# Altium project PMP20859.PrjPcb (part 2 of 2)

## Sheet PMP20859_RevF_SH3.SchDoc: Synchronous Flyback Converter
size 431 x 279 mm; Date: Not shown in title block; ApprovedBy: Not shown in title block; CheckedBy: Not shown in title block; Author: Not shown in title block; CompanyName: Not shown in title block; Engineer: Not shown in title block; Organization: Not shown in title block; Address1: Not shown in title block; Address2: Not shown in title block; Address3: Not shown in title block; Address4: Not shown in title block; DocumentNumber: 3; Revision: Use project parameter SCH_Rev; SheetNumber: 3; SheetTotal: 3; PageSetup: Record=PageOptions¦CenterHorizontal=True¦CenterVertical=True¦PrintScale=1.00¦XCorrection=1.00¦YCorrection=1.00¦PrintKind=0¦BorderSize=5000000¦LeftOffset=0¦BottomOffset=0¦Orientation=2¦PaperLength=1000¦PaperWidth=1000¦Scale=100¦PaperSource=15¦PrintQuality=600¦MediaType=1¦DitherType=10¦PaperKind=Letter¦PrintScaleMode=1
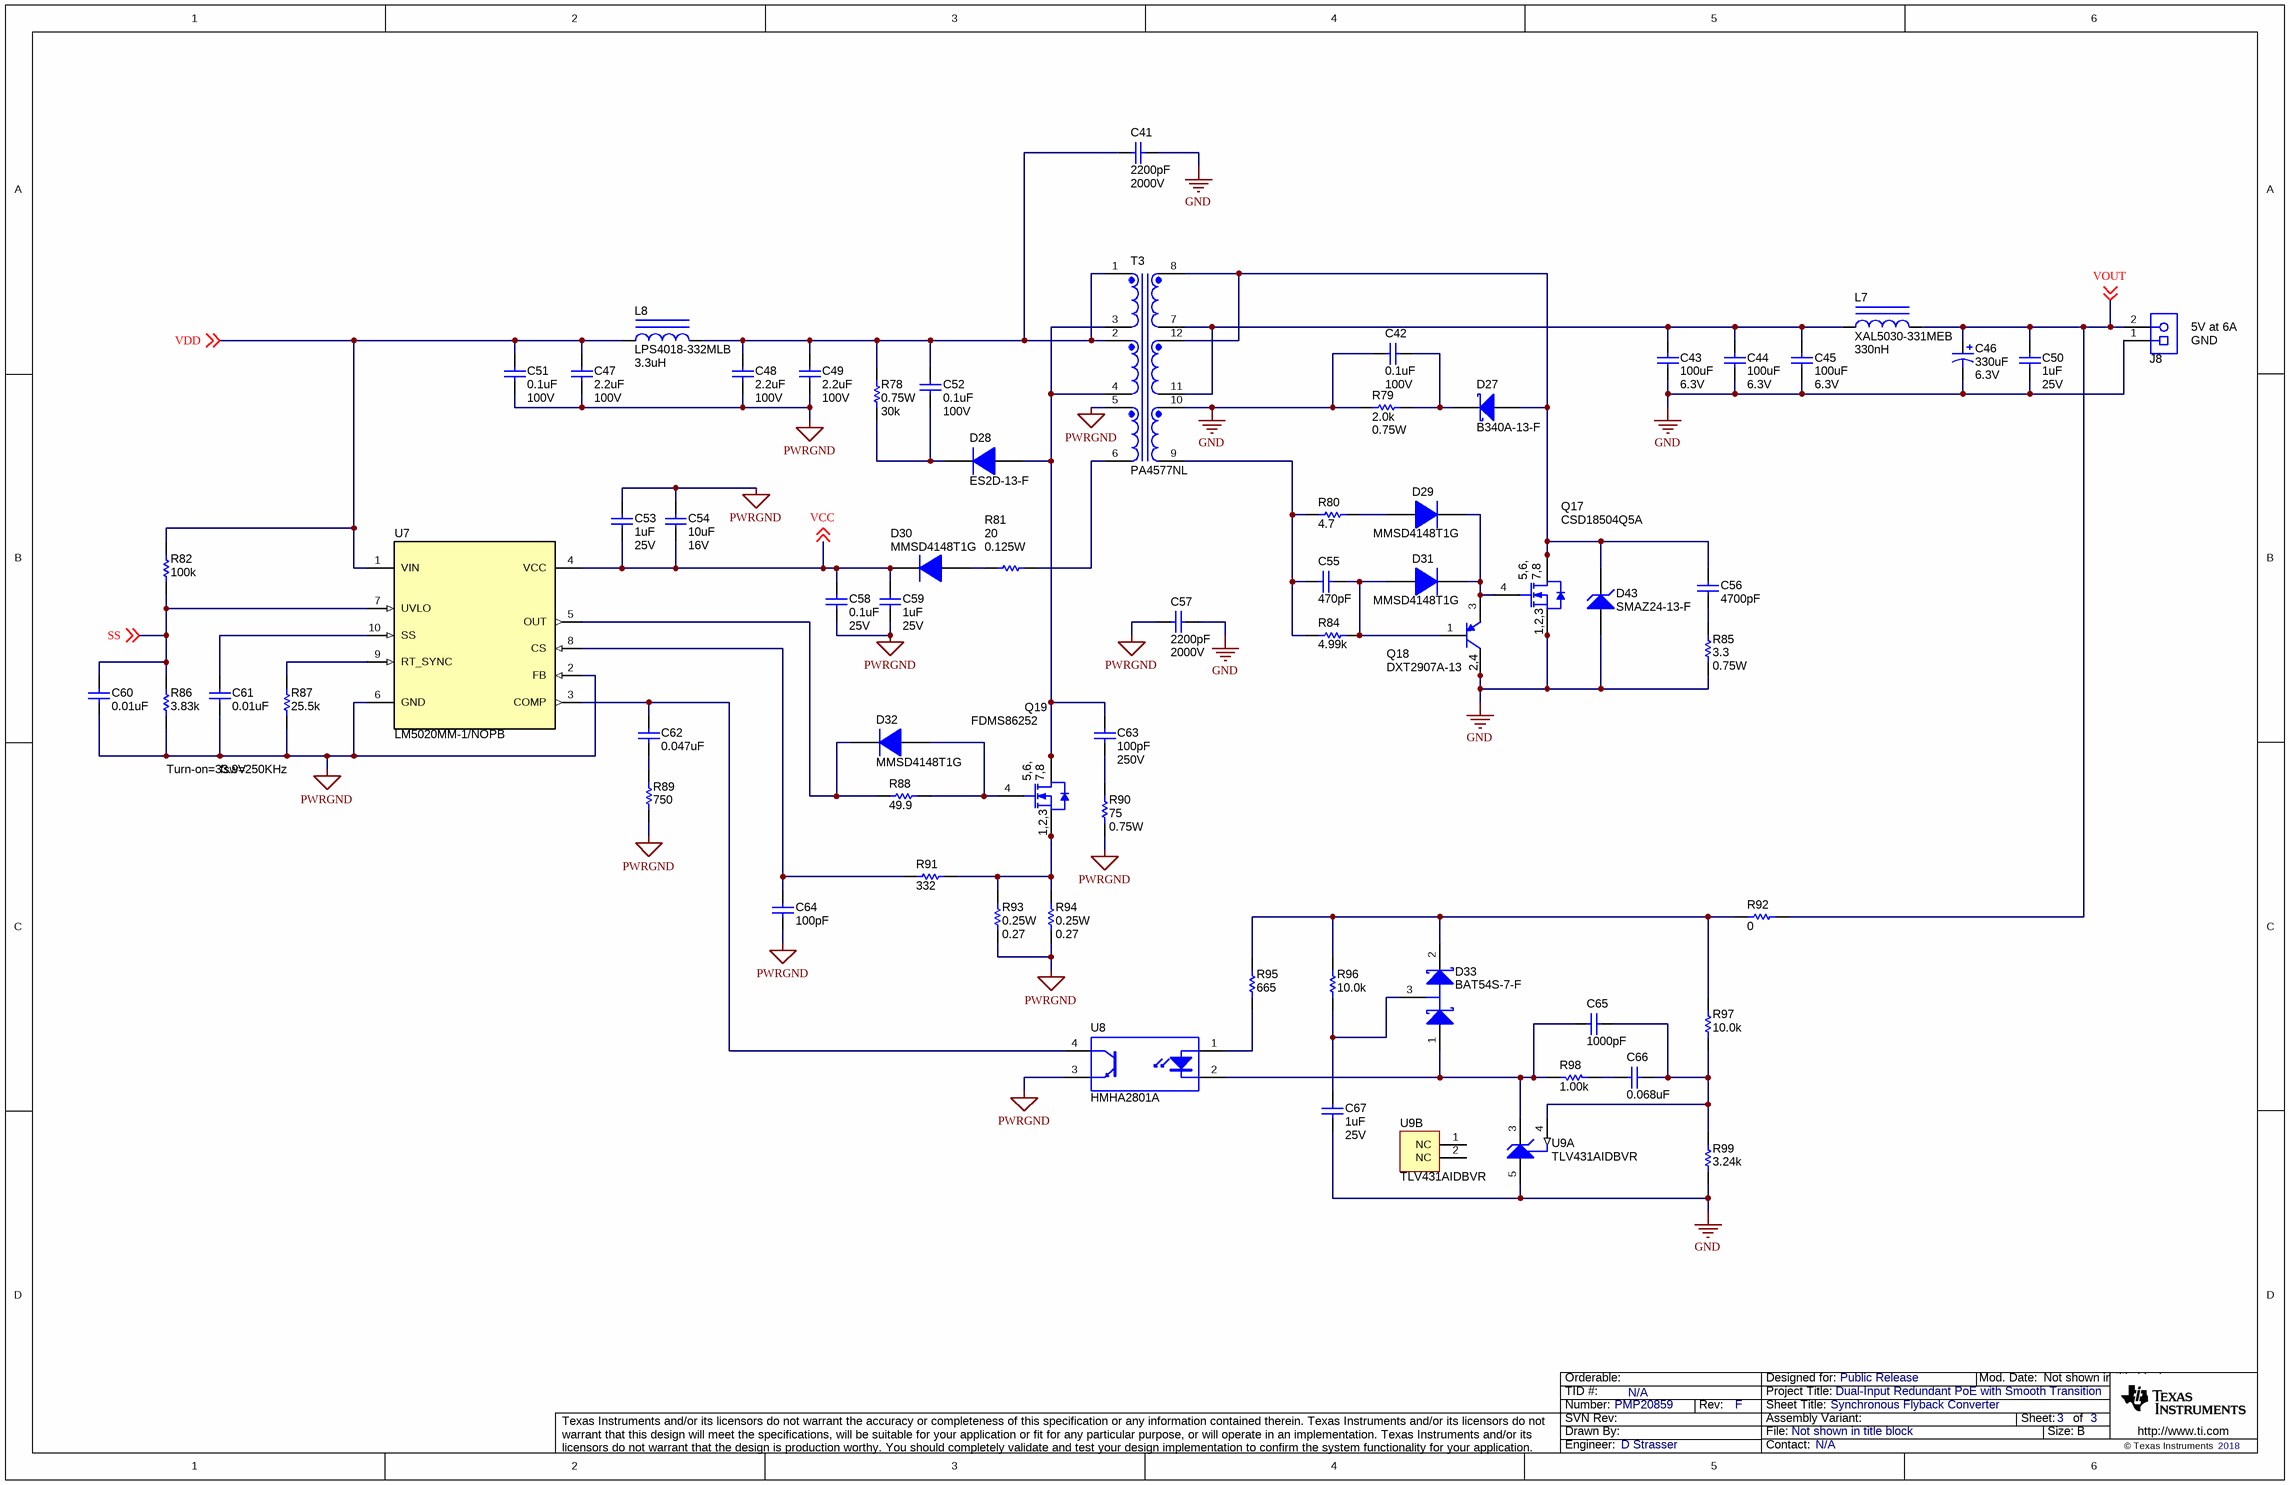
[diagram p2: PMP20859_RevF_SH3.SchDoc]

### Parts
C41  ValueDisplayed: 2200pF  Value2: 2000V  [1812]  (hidden comment: Capacitor)
C42  ValueDisplayed: 0.1uF  Value2: 100V  [0805_HV]  (hidden comment: Capacitor)
C43  ValueDisplayed: 100uF  Value2: 6.3V  [1210_280]  (hidden comment: Capacitor)
C44  ValueDisplayed: 100uF  Value2: 6.3V  [1210_280]  (hidden comment: Capacitor)
C45  ValueDisplayed: 100uF  Value2: 6.3V  [1210_280]  (hidden comment: Capacitor)
C46  ValueDisplayed: 330uF  Value2: 6.3V  [SM_RADIAL_10AMM]  (hidden comment: Cap_Polarized)
C47  ValueDisplayed: 2.2uF  Value2: 100V  [1210_270]  (hidden comment: Capacitor)
C48  ValueDisplayed: 2.2uF  Value2: 100V  [1210_270]  (hidden comment: Capacitor)
C49  ValueDisplayed: 2.2uF  Value2: 100V  [1210_270]  (hidden comment: Capacitor)
C50  ValueDisplayed: 1uF  Value2: 25V  [0805_HV]  (hidden comment: Capacitor)
C51  ValueDisplayed: 0.1uF  Value2: 100V  [0805_HV]  (hidden comment: Capacitor)
C52  ValueDisplayed: 0.1uF  Value2: 100V  [0805_HV]  (hidden comment: Capacitor)
C53  ValueDisplayed: 1uF  Value2: 25V  [0805_HV]  (hidden comment: Capacitor)
C54  ValueDisplayed: 10uF  Value2: 16V  [1206_190]  (hidden comment: Capacitor)
C55  ValueDisplayed: 470pF  [0603L]  (hidden comment: Capacitor)
C56  ValueDisplayed: 4700pF  [0603L]  (hidden comment: Capacitor)
C57  ValueDisplayed: 2200pF  Value2: 2000V  [1812]  (hidden comment: Capacitor)
C58  ValueDisplayed: 0.1uF  VDC_V: 25V  [0603]  (hidden comment: C1608X7R1E104K080AA)
C59  ValueDisplayed: 1uF  Value2: 25V  [0805_HV]  (hidden comment: Capacitor)
C60  ValueDisplayed: 0.01uF  [0603L]  (hidden comment: Capacitor)
C61  ValueDisplayed: 0.01uF  [0603L]  (hidden comment: Capacitor)
C62  ValueDisplayed: 0.047uF  [0603L]  (hidden comment: Capacitor)
C63  ValueDisplayed: 100pF  Value2: 250V  [0805_HV]  (hidden comment: Capacitor)
C64  ValueDisplayed: 100pF  [0603L]  (hidden comment: Capacitor)
C65  ValueDisplayed: 1000pF  [0603L]  (hidden comment: Capacitor)
C66  ValueDisplayed: 0.068uF  [0603L]  (hidden comment: Capacitor)
C67  ValueDisplayed: 1uF  Value2: 25V  [0805_HV]  (hidden comment: Capacitor)
D27  B340A-13-F  [SMA]
D28  ES2D-13-F  [SMB]
D29  MMSD4148T1G  [SOD-123]
D30  MMSD4148T1G  [SOD-123]
D31  MMSD4148T1G  [SOD-123]
D32  MMSD4148T1G  [SOD-123]
D33  BAT54S-7-F  [SOT-23]
D43  SMAZ24-13-F  [SMA]
J8  ED555/2DS  [TERM_BLK_ED555-2DS]  (value not drawn)
L7  XAL5030-331MEB  ValueDisplayed: 330nH  [XAL5030]
L8  LPS4018-332MLB  value 3.3uH  [LPS4018]
Q17  CSD18504Q5A  [DQJ0008A]
Q18  DXT2907A-13  [SOT-89-3]
Q19  FDMS86252  [TRANS_Fairchild_PQFN08A]
R78  Value2: 0.75W  ValueDisplayed: 30k  [2010L]  (hidden comment: Resistor)
R79  ValueDisplayed: 2.0k  Value2: 0.75W  [2010L]  (hidden comment: Resistor)
R80  ValueDisplayed: 4.7  [0603L]  (hidden comment: Resistor)
R81  value 20  Value2: 0.125W  [0805_HV]  (hidden comment: Resistor)
R82  ValueDisplayed: 100k  [0603L]  (hidden comment: Resistor)
R84  value 4.99k  [0603L]  (hidden comment: Resistor)
R85  ValueDisplayed: 3.3  Value2: 0.75W  [2010L]  (hidden comment: Resistor)
R86  ValueDisplayed: 3.83k  [0603L]  (hidden comment: Resistor)
R87  ValueDisplayed: 25.5k  [0603L]  (hidden comment: Resistor)
R88  ValueDisplayed: 49.9  [0603L]  (hidden comment: Resistor)
R89  ValueDisplayed: 750  [0603L]  (hidden comment: Resistor)
R90  ValueDisplayed: 75  Value2: 0.75W  [2010L]  (hidden comment: Resistor)
R91  value 332  [0603L]  (hidden comment: Resistor)
R92  ValueDisplayed: 0  [0603]  (hidden comment: Resistor)
R93  Value2: 0.25W  ValueDisplayed: 0.27  [1206L]  (hidden comment: Resistor)
R94  Value2: 0.25W  ValueDisplayed: 0.27  [1206L]  (hidden comment: Resistor)
R95  ValueDisplayed: 665  [0603L]  (hidden comment: Resistor)
R96  ValueDisplayed: 10.0k  [0603L]  (hidden comment: Resistor)
R97  ValueDisplayed: 10.0k  [0603L]  (hidden comment: Resistor)
R98  ValueDisplayed: 1.00k  [0603L]  (hidden comment: Resistor)
R99  ValueDisplayed: 3.24k  [0603L]  (hidden comment: Resistor)
T3  PA4577NL  [Pulse_PA4577NL]
U7  LM5020MM-1/NOPB  [DGS0010A_N]
U8  HMHA2801A  [MFP04A]
U9  TLV431AIDBVR  [DBV0005A_N]  (parts A,B of 2)

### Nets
GND: C41.2 C42.1 C43.2 C44.2 C45.2 C46.2(-) C50.2 C57.2 C67.2 D43.2(A) J8.1 Q17.1(S) Q17.2(S) Q17.3(S) Q18.2(C) Q18.4(C) R79.2 R85.1 R99.1 T3.10 U9.5(ANODE)
PWRGND: C47.2 C48.2 C49.2 C51.2 C53.1 C54.2 C57.1 C58.2 C59.2 C60.1 C61.1 C64.2 R86.1 R87.1 R89.1 R90.1 R93.1 R94.1 T3.5 U7.2(FB) U7.6(GND) U8.3(E)
SS: C60.2 R82.1 R86.2 U7.7(UVLO) ; off-sheet SS
VCC: C53.2 C54.1 C58.1 C59.1 D30.1(K) U7.4(VCC) ; off-sheet VCC
VDD: C47.1 C51.1 L8.1 R82.2 U7.1(VIN) ; off-sheet VDD
VOUT: C46.1(+) C50.1 J8.2 L7.2 R92.1 ; off-sheet VOUT
NetC41_1: C41.1 C48.1 C49.1 C52.1 L8.2 R78.2 T3.1 T3.2
NetC42_2: C42.2 D27.1(K) R79.1
NetC43_1: C43.1 C44.1 C45.1 L7.1 T3.7 T3.11
NetC52_2: C52.2 D28.1(K) R78.1
NetC55_1: C55.1 R80.2 R84.2 T3.9
NetC55_2: C55.2 D31.2(A) Q18.1(B) R84.1
NetC56_1: C56.1 R85.2
NetC56_2: C56.2 D27.2(A) D43.1(K) Q17.5(D) Q17.6(D) Q17.7(D) Q17.8(D) Q17.9(D) T3.8 T3.12
NetC61_2: C61.2 U7.10(SS)
NetC62_1: C62.1 R89.2
NetC62_2: C62.2 U7.3(COMP) U8.4(C)
NetC63_1: C63.1 D28.2(A) Q19.5(D) Q19.6(D) Q19.7(D) Q19.8(D) T3.3 T3.4
NetC63_2: C63.2 R90.2
NetC64_1: C64.1 R91.1 U7.8(CS)
NetC65_1: C65.1 C66.2 R97.2 R99.2 U9.4(REF)
NetC65_2: C65.2 D33.1(A) R98.2 U8.2(K) U9.3(CATHODE)
NetC66_1: C66.1 R98.1
NetC67_1: C67.1 D33.3(C) R96.1
NetD29_1: D29.1(K) D31.1(K) Q17.4(G) Q18.3(E)
NetD29_2: D29.2(A) R80.1
NetD30_2: D30.2(A) R81.1
NetD32_1: D32.1(K) R88.2 U7.5(OUT)
NetD32_2: D32.2(A) Q19.4(G) R88.1
NetD33_2: D33.2(K) R92.2 R95.2 R96.2 R97.1
NetQ19_1: Q19.1(S) Q19.2(S) Q19.3(S) R91.2 R93.2 R94.2
NetR81_2: R81.2 T3.6
NetR87_2: R87.2 U7.9(RT_SYNC)
NetR95_1: R95.1 U8.1(A)

Not connected (* = marked no-connect by the designer): U9 1(NC) 2(NC)

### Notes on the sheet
- (near J8) GND
- (near J8) 5V at 6A
- Turn-on=33.9V
- fsw=250KHz

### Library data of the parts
C41 C57 = CMP-0009358-2: CAP, CERM, 2200 pF, 2000 V, +/- 10%, X7R, 1812; PartNumber: C4532X7R3D222K130KA; Manufacturer: TDK; Polarized: N; Value: 2200pF; U/M: EA; Cap_F: 2.2nF; Value1: Unknown; VDC_V: 2kV; TaMin_C: -55°C; TaMax_C: 125°C; SizeArea_mm2: 14.4; SizeAreaWB_mm2: 23.1; SizeX_mm: 4.5; SizeY_mm: 3.2; SizeZ_mm: 1.35; AEC Category: Q200
C42 C51 C52 = CMP-0007886-2: CAP, CERM, 0.1 uF, 100 V, +/- 10%, X7R, 0805; PartNumber: C2012X7R2A104K125AA; Manufacturer: TDK; Polarized: N; Value: 0.1uF; U/M: EA; Cap_F: 100nF; ESR_ohm: 0.020726; Value1: 0.020726 ohm; IRMS_A: 1.456A; TaMin_C: -55°C; TaMax_C: 125°C; Cap_Case: 0805; AEC Category: Q200; SizeArea_mm2: 2.5; SizeAreaWB_mm2: 6.75; SizeX_mm: 2; SizeY_mm: 1.25; SizeZ_mm: 1.45
C43-C45 = CMP-0009098-2: CAP, CERM, 100 uF, 6.3 V, +/- 20%, X5R, 1210; PartNumber: C3225X5R0J107M250AC; Manufacturer: TDK; Polarized: N; Value: 100uF; U/M: EA; Cap_F: 100µF; ESR_ohm: 5.496m; Value1: 0.005496 ohm; IRMS_A: 3.13651A; TaMin_C: -55°C; TaMax_C: 85°C; SizeArea_mm2: 8; SizeAreaWB_mm2: 14.7; SizeX_mm: 3.2; SizeY_mm: 2.5; SizeZ_mm: 2.8; AEC Category: Q200
C46 = CMP-0012153-3: CAP, Aluminum Polymer, 330 uF, 6.3 V, +/- 20%, 0.025 ohm, 10x10.3 SMD; PartNumber: 6SVP330M; Manufacturer: Panasonic; Polarized: Y; CompType: Capacitor; Value: 330uF; Cap_F: 330µF; ESR_ohm: 0.025; IRMS_A: 3.7A; TaMin_C: -55°C; TaMax_C: 105°C; Cap_Case: 10.3x10.3x7.9; AEC Category: Q200; SizeArea_mm2: 113.3; SizeAreaWB_mm2: 159.9; SizeX_mm: 11; SizeY_mm: 10.3; SizeZ_mm: 7.7
C47-C49 = CMP-0009232-2: CAP, CERM, 2.2 uF, 100 V, +/- 10%, X7R, 1210; PartNumber: GRM32ER72A225KA35L; Manufacturer: MuRata; Polarized: N; Value: 2.2uF; U/M: EA; Cap_F: 2.2µF; ESR_ohm: 7m; Value1: 0.007 ohm; IRMS_A: 4.4A; TaMin_C: -55°C; TaMax_C: 125°C; Cap_Case: 1210; SizeArea_mm2: 8; SizeAreaWB_mm2: 14.7; SizeX_mm: 3.2; SizeY_mm: 2.5; SizeZ_mm: 2.7; AEC Category: Q200
C50 C53 C59 C67 = CMP-0008336-2: CAP, CERM, 1 uF, 25 V, +/- 10%, X7R, 0805; PartNumber: GRM21BR71E105KA99L; Manufacturer: MuRata; Polarized: N; Value: 1uF; U/M: EA; Cap_F: 1µF; Value1: Unknown; TaMin_C: -55°C; TaMax_C: 125°C; Cap_Case: 0805; SizeArea_mm2: 2.5; SizeAreaWB_mm2: 6.75; SizeX_mm: 2; SizeY_mm: 1.25; SizeZ_mm: 1.45; AEC Category: Q200
C54 = CMP-0008690-2: CAP, CERM, 10 uF, 16 V, +/- 10%, X7R, 1206_190; PartNumber: C3216X7R1C106K160AC; Manufacturer: TDK; Polarized: N; Value: 10uF; U/M: EA; Cap_F: 10µF; Value1: Unknown; TaMin_C: -55°C; TaMax_C: 125°C; Cap_Case: 1206; AEC Category: Q200; SizeArea_mm2: 5.12; SizeAreaWB_mm2: 10.92; SizeX_mm: 3.2; SizeY_mm: 1.6; SizeZ_mm: 1.9
C55 = CMP-0007221-4: CAP, CERM, 470 pF, 50 V, +/- 5%, C0G/NP0, 0603; PartNumber: GRM1885C1H471JA01D; Manufacturer: MuRata; Polarized: N; Value: 470pF; U/M: EA; Value1: Unknown; VDC_V: 50V; TaMin_C: -55°C; TaMax_C: 125°C; Cap_Case: 0603; SizeArea_mm2: 1.28; SizeAreaWB_mm2: 4.68; SizeX_mm: 1.6; SizeY_mm: 0.8; SizeZ_mm: 1; AEC Category: Q200
C56 = CMP-0007456-4: CAP, CERM, 4700 pF, 50 V, +/- 10%, X7R, 0603; PartNumber: GRM188R71H472KA01D; Manufacturer: MuRata; Polarized: N; Value: 4700pF; U/M: EA; Cap_F: 4.7nF; Value1: Unknown; VDC_V: 50V; TaMin_C: -55°C; TaMax_C: 125°C; Cap_Case: 0603; AEC Category: Q200; SizeArea_mm2: 1.28; SizeAreaWB_mm2: 4.68; SizeX_mm: 1.6; SizeY_mm: 0.8; SizeZ_mm: 1
C58 = CMP-0007039-5: CAP, CERM, 0.1 uF, 25 V, +/- 10%, X7R, 0603; Manufacturer: TDK; Polarized: N; CompType: Capacitor; Value: 0.1uF; U/M: EA; Cap_F: 100nF; Value1: Unknown; TaMin_C: -55°C; TaMax_C: 125°C; SizeArea_mm2: 1.28; SizeAreaWB_mm2: 4.68; SizeX_mm: 1.6; SizeY_mm: 0.8; SizeZ_mm: 1; AEC Category: Q200
C60 C61 = CMP-0007043-4: CAP, CERM, 0.01 uF, 50 V, +/- 10%, X7R, 0603; PartNumber: C1608X7R1H103K080AA; Manufacturer: TDK; Polarized: N; Value: 0.01uF; U/M: EA; Cap_F: 10nF; ESR_ohm: 0.0539; Value1: 0.0539 ohm; VDC_V: 50V; TaMin_C: -55°C; TaMax_C: 125°C; Cap_Case: 0603; SizeArea_mm2: 1.28; SizeAreaWB_mm2: 4.68; SizeX_mm: 1.6; SizeY_mm: 0.8; SizeZ_mm: 1; AEC Category: Q200
C62 = CMP-0007049-4: CAP, CERM, 0.047 uF, 50 V, +/- 10%, X7R, 0603; PartNumber: C1608X7R1H473K080AA; Manufacturer: TDK; Polarized: N; U/M: EA; Cap_F: 47nF; ESR_ohm: 0.049007; Value1: 0.049007 ohm; VDC_V: 50V; IRMS_A: 7.67528dA; TaMin_C: -55°C; TaMax_C: 125°C; Cap_Case: 0603; AEC Category: Q200; SizeArea_mm2: 1.28; SizeAreaWB_mm2: 4.68; SizeX_mm: 1.6; SizeY_mm: 0.8; SizeZ_mm: 1
C63 = CMP-0008236-2: CAP, CERM, 100 pF, 250 V, +/- 5%, C0G/NP0, 0805; PartNumber: GRM21A5C2E101JW01D; Manufacturer: MuRata; Polarized: N; Value: 100pF; U/M: EA; Value1: Unknown; TaMin_C: -55°C; TaMax_C: 125°C; Cap_Case: 0805; AEC Category: Q200; SizeArea_mm2: 2.5; SizeAreaWB_mm2: 6.75; SizeX_mm: 2; SizeY_mm: 1.25; SizeZ_mm: 1.45
C64 = CMP-0007171-4: CAP, CERM, 100 pF, 50 V, +/- 5%, C0G/NP0, 0603; PartNumber: GRM1885C1H101JA01D; Manufacturer: MuRata; Polarized: N; Value: 100pF; U/M: EA; Value1: Unknown; VDC_V: 50V; TaMin_C: -55°C; TaMax_C: 125°C; Cap_Case: 0603; AEC Category: Q200; SizeArea_mm2: 1.28; SizeAreaWB_mm2: 4.68; SizeX_mm: 1.6; SizeY_mm: 0.8; SizeZ_mm: 1
C65 = CMP-0007432-5: CAP, CERM, 1000 pF, 50 V, +/- 10%, X7R, 0603; PartNumber: GRM188R71H102KA01D; Manufacturer: MuRata; Polarized: N; Value: 1000pF; U/M: EA; Cap_F: 1nF; Value1: Unknown; VDC_V: 50V; TaMin_C: -55°C; TaMax_C: 125°C; Cap_Case: 0603; AEC Category: Q200; SizeArea_mm2: 1.28; SizeAreaWB_mm2: 4.68; SizeX_mm: 1.6; SizeY_mm: 0.8; SizeZ_mm: 1
C66 = CMP-0007428-4: CAP, CERM, 0.068 uF, 25 V, +/- 10%, X7R, 0603; PartNumber: GRM188R71E683KA01D; Manufacturer: MuRata; Polarized: N; U/M: EA; Cap_F: 68nF; Value1: Unknown; VDC_V: 25V; TaMin_C: -55°C; TaMax_C: 125°C; Cap_Case: 0603; AEC Category: Q200; SizeArea_mm2: 1.28; SizeAreaWB_mm2: 4.68; SizeX_mm: 1.6; SizeY_mm: 0.8; SizeZ_mm: 1
D27 = CMP-0028353-1: Diode, Schottky, 40 V, 3 A, SMA; Manufacturer: Diodes Inc.; U/M: EA; Vf_V: 5dV; Value: 40V; Value1: 3A; Value2: 0.5V; TJmax_C: 125°C; RJC_CperW: 25; AEC Category: Q101; Green_Lifecycle: Active; Green_REACh: Passed; SizeArea_mm2: 16.3228; SizeAreaWB_mm2: 37.3428; SizeX_mm: 5.59; SizeY_mm: 2.92; SizeZ_mm: 2.87
D28 = CMP-0076890-1: Diode, Ultrafast, 200 V, 2 A, SMB; Manufacturer: Diodes Inc.; Value: 200V; U/M: EA; Vf_V: 9.2dV; Value1: 2A; Value2: 0.92V; TJmax_C: 150°C; RJC_CperW: 20.0; AEC Category: Q101; Green_Lifecycle: Active; Green_REACh: Passed; SizeArea_mm2: 21.336; SizeAreaWB_mm2: 44.156; SizeX_mm: 5.6; SizeY_mm: 3.81; SizeZ_mm: 2.6
D29-D32 = CMP-0029032-1: Diode, Switching, 100 V, 0.2 A, SOD-123; Manufacturer: ON Semiconductor; Value: 100V; U/M: EA; Vf_V: 1V; Value1: 0.2A; Io_A: 2dA; TJmax_C: 150°C; AEC Category: Q101; Green_Lifecycle: Active; Green_REACh: Passed; SizeArea_mm2: 6.545; SizeAreaWB_mm2: 13.095; SizeX_mm: 3.85; SizeY_mm: 1.7; SizeZ_mm: 1.35
D33 = CMP-0028456-1: Diode, Schottky, 30 V, 0.2 A, SOT-23; Manufacturer: Diodes Inc.; Value: 30V; U/M: EA; Vf_V: 6.5dV; Value1: 0.2A; Value2: 0.65V; Io_A: 2dA; TJmax_C: 125°C; AEC Category: Q101; Green_Lifecycle: Active; Green_REACh: Passed; SizeArea_mm2: 7.5; SizeAreaWB_mm2: 14; SizeX_mm: 2.5; SizeY_mm: 3; SizeZ_mm: 1.1
D43 = CMP-0005528-4: Diode, Zener, 24 V, 1 W, SMA; Manufacturer: Diodes Inc.; AEC Qualified: N; SizeY_mm: 2.92; RJA_CperW: 100; Value: 24V; SizeX_mm: 5.59; SizeArea_mm2: 16.3228; AEC Category: Q101; Value1: 1W; SizeAreaWB_mm2: 37.3428; SizeZ_mm: 2.87
J8 = CMP-0074913-1: Terminal Block, 3.5mm Pitch, 2x1, TH; Manufacturer: On-Shore Technology; Cert_CULUS: Y; CNHeader: False; ContactFinish: Brass; CT: True; Current_A: 6A; Gender: Female; Green_Lifecycle: Active; Green_REACh: Passed; Pitch_mm: 3.5; Row_Count: 1; Shrouded: N; Voltage_V: 150V
L7 = CMP-0061002-1: Inductor, Shielded, Composite, 330 nH, 19.2 A, 0.0032 ohm, SMD; Manufacturer: Coilcraft; Value: 330nH; Imax_A: 19.2A; Irms: 19.2A @ 40C rise; Isat: 26A @ 30% inductance drop; DCR_ohm: 3.2m; AEC Category: Q200; Green_Lifecycle: Not Set; Green_REACh: Incomplete; SizeArea_mm2: 28.9344; SizeAreaWB_mm2: 54.4544; SizeX_mm: 5.28; SizeY_mm: 5.48; SizeZ_mm: 3.1
L8 = CMP-0060473-1: Inductor, Shielded Drum Core, Ferrite, 3.3 uH, 1.9 A, 0.08 ohm, SMD; Manufacturer: Coilcraft; Ind_H: 3.3µH; Imax_A: 1.9A; Irms: 1.9A @ 40C rise; Isat: 2A @ 30% inductance drop; DCR_ohm: 0.08; AEC Category: Q200; Green_Lifecycle: Not Set; Green_REACh: Incomplete; SizeArea_mm2: 15.21; SizeAreaWB_mm2: 24.01; SizeX_mm: 3.9; SizeZ_mm: 1.7
Q17 = CMP-0000708-1: MOSFET, N-CH, 40 V, 15 A, DQJ0008A (VSONP-8); Manufacturer: Texas Instruments; Alternate Manufacturer: None; U/M: EA; ChType: N; Value: 40V; Value1: 0.009; Rdson45_ohm: 9.8m; Value2: 7.7 nC; QgTyp_nC: 7.7; Vgs_V: 20V; IdsMax_A: 15A; SizeAreaWB_mm2: 55.2; SizeArea_mm2: 29.4; SizeX_mm: 6; SizeY_mm: 4.9; SizeZ_mm: 1.1; AEC Category: Q101
Q18 = CMP-0000356-2: Transistor, PNP, 60 V, 0.6 A, AEC-Q101, SOT-89; Manufacturer: Diodes Inc.; CompType: BJT; PNP: 1; NPN: 0; Vceo_V: 60V; Vcesat1_V: 1.3dV; Value: 60 V; IcRated_A: 6dA; Value1: 0.6 A; HfeMax: 300; TaMin_C: -55°C; TaMax_C: 150°C; U/M: EA; AEC Category: Q101; AEC Qualified: Y; SizeArea_mm2: 18.45; SizeAreaWB_mm2: 28.05; SizeX_mm: 4.1; SizeY_mm: 4.5; SizeZ_mm: 1.5
Q19 = CMP-0001058-1: MOSFET, N-CH, 150 V, 4.6 A, PQFN08A; Manufacturer: Fairchild Semiconductor; Alternate Manufacturer: None; Value: 150V; U/M: EA; ChType: N; Value1: 0; Rdson45_ohm: 0.07; Value2: 11 nC; QgTyp_nC: 11; Vgs_V: 20V; IdsMax_A: 4.6A; AEC Category: Q101; SizeArea_mm2: 30; SizeAreaWB_mm2: 56; SizeX_mm: 5; SizeY_mm: 6; SizeZ_mm: 1.1
R78 = CMP-0016116-3: RES, 30 k, 5%, 0.75 W, AEC-Q200 Grade 0, 2010; PartNumber: CRCW201030K0JNEF; Manufacturer: Vishay-Dale; Value: 30k; Value_Code: 30k0; Power_W: 750mW; VDC_V: 400V; TempCo: 200 ppm/C; EIA_Code: E24; SizeArea_mm2: 12.5; SizeX_mm: 5; SizeY_mm: 2.5; SizeZ_mm: 1.66; AEC Category: Q200; AEC Qualified: Y; AEC Grade: 0
R79 = CMP-0016106-3: RES, 2.0 k, 5%, 0.75 W, AEC-Q200 Grade 0, 2010; PartNumber: CRCW20102K00JNEF; Manufacturer: Vishay-Dale; Value: 2.0k; Res_ohm: 2k; Value_Code: 2k00; Power_W: 750mW; VDC_V: 400V; TempCo: 200 ppm/C; EIA_Code: E24; AEC Category: Q200; AEC Qualified: Y; AEC Grade: 0; SizeArea_mm2: 12.5; SizeX_mm: 5; SizeY_mm: 2.5; SizeZ_mm: 1.66
R80 = CMP-0025821-4: RES, 4.7, 5%, 0.1 W, AEC-Q200 Grade 0, 0603; PartNumber: CRCW06034R70JNEA; Manufacturer: Vishay-Dale; Value: 4.7; Value_Code: 4R70; Power_W: 100mW; Value2: 0.1W; VDC_V: 75V; TempCo: 200 ppm/C; EIA_Code: E24; AEC Category: Q200; AEC Qualified: Y; AEC Grade: 0; SizeArea_mm2: 1.28; SizeX_mm: 1.6; SizeY_mm: 0.8; SizeZ_mm: 1
R81 = CMP-0020497-3: RES, 20, 5%, 0.125 W, AEC-Q200 Grade 0, 0805; PartNumber: CRCW080520R0JNEA; Manufacturer: Vishay-Dale; Value_Code: 20R0; Power_W: 125mW; VDC_V: 150V; TempCo: 200 ppm/C; EIA_Code: E24; AEC Category: Q200; AEC Grade: 0; AEC Qualified: Y; SizeArea_mm2: 2.5; SizeX_mm: 2; SizeY_mm: 1.25; SizeZ_mm: 1.45
R82 = CMP-0021990-4: RES, 100 k, 1%, 0.1 W, AEC-Q200 Grade 0, 0603; PartNumber: CRCW0603100KFKEA; Manufacturer: Vishay-Dale; Value: 100k; Power_W: 100mW; Value2: 0.1W; VDC_V: 75V; TempCo: 100 ppm/C; EIA_Code: E96; AEC Category: Q200; AEC Grade: 0; AEC Qualified: Y; SizeArea_mm2: 1.28; SizeX_mm: 1.6; SizeY_mm: 0.8; SizeZ_mm: 1
R84 = CMP-0022458-4: RES, 4.99 k, 1%, 0.1 W, AEC-Q200 Grade 0, 0603; PartNumber: CRCW06034K99FKEA; Manufacturer: Vishay-Dale; Value_Code: 4k99; Power_W: 100mW; Value2: 0.1W; VDC_V: 75V; TempCo: 100 ppm/C; EIA_Code: E96; AEC Category: Q200; AEC Grade: 0; AEC Qualified: Y; SizeArea_mm2: 1.28; SizeX_mm: 1.6; SizeY_mm: 0.8; SizeZ_mm: 1
R85 = CMP-0016136-3: RES, 3.3, 5%, 0.75 W, AEC-Q200 Grade 0, 2010; PartNumber: CRCW20103R30JNEF; Manufacturer: Vishay-Dale; Value: 3.3; Value_Code: 3R30; Power_W: 750mW; VDC_V: 400V; TempCo: 200 ppm/C; EIA_Code: E24; AEC Category: Q200; AEC Qualified: Y; AEC Grade: 0; SizeArea_mm2: 12.5; SizeX_mm: 5; SizeY_mm: 2.5; SizeZ_mm: 1.66
R86 = CMP-0022381-4: RES, 3.83 k, 1%, 0.1 W, AEC-Q200 Grade 0, 0603; PartNumber: CRCW06033K83FKEA; Manufacturer: Vishay-Dale; Value: 3.83k; Value_Code: 3k83; Power_W: 100mW; Value2: 0.1W; VDC_V: 75V; TempCo: 100 ppm/C; EIA_Code: E96; AEC Category: Q200; AEC Qualified: Y; AEC Grade: 0; SizeArea_mm2: 1.28; SizeX_mm: 1.6; SizeY_mm: 0.8; SizeZ_mm: 1
R87 = CMP-0022242-4: RES, 25.5 k, 1%, 0.1 W, AEC-Q200 Grade 0, 0603; PartNumber: CRCW060325K5FKEA; Manufacturer: Vishay-Dale; Value: 25.5k; Value_Code: 25k5; Power_W: 100mW; Value2: 0.1W; VDC_V: 75V; TempCo: 100 ppm/C; EIA_Code: E96; AEC Category: Q200; AEC Grade: 0; AEC Qualified: Y; SizeArea_mm2: 1.28; SizeX_mm: 1.6; SizeY_mm: 0.8; SizeZ_mm: 1
R88 = CMP-0022448-4: RES, 49.9, 1%, 0.1 W, AEC-Q200 Grade 0, 0603; PartNumber: CRCW060349R9FKEA; Manufacturer: Vishay-Dale; Value: 49.9; Value_Code: 49R9; Power_W: 100mW; Value2: 0.1W; VDC_V: 75V; TempCo: 100 ppm/C; EIA_Code: E96; AEC Category: Q200; AEC Qualified: Y; AEC Grade: 0; SizeArea_mm2: 1.28; SizeX_mm: 1.6; SizeY_mm: 0.8; SizeZ_mm: 1
R89 = CMP-0022588-5: RES, 750, 1%, 0.1 W, AEC-Q200 Grade 0, 0603; PartNumber: CRCW0603750RFKEA; Manufacturer: Vishay-Dale; Value: 750; Value_Code: 750R; Power_W: 100mW; Value2: 0.1W; VDC_V: 75V; TempCo: 100 ppm/C; EIA_Code: E96; AEC Category: Q200; AEC Qualified: Y; AEC Grade: 0; SizeArea_mm2: 1.28; SizeX_mm: 1.6; SizeY_mm: 0.8; SizeZ_mm: 1
R90 = CMP-0016178-3: RES, 75, 5%, 0.75 W, AEC-Q200 Grade 0, 2010; PartNumber: CRCW201075R0JNEF; Manufacturer: Vishay-Dale; Value: 75; Value_Code: 75R0; Power_W: 750mW; VDC_V: 400V; TempCo: 200 ppm/C; EIA_Code: E24; SizeArea_mm2: 12.5; SizeX_mm: 5; SizeY_mm: 2.5; SizeZ_mm: 1.66; AEC Category: Q200; AEC Qualified: Y; AEC Grade: 0
R91 = CMP-0022337-5: RES, 332, 1%, 0.1 W, AEC-Q200 Grade 0, 0603; PartNumber: CRCW0603332RFKEA; Manufacturer: Vishay-Dale; Value_Code: 332R; Power_W: 100mW; Value2: 0.1W; VDC_V: 75V; TempCo: 100 ppm/C; EIA_Code: E96; AEC Category: Q200; AEC Grade: 0; AEC Qualified: Y; SizeArea_mm2: 1.28; SizeX_mm: 1.6; SizeY_mm: 0.8; SizeZ_mm: 1
R92 = CMP-0025697-4: RES, 0, 5%, 0.1 W, AEC-Q200 Grade 0, 0603; PartNumber: CRCW06030000Z0EA; Manufacturer: Vishay-Dale; Value: 0; Value_Code: 0000; Power_W: 100mW; Value2: 0.1W; VDC_V: 75V; TempCo: 200 ppm/C; EIA_Code: E24; SizeArea_mm2: 1.28; SizeX_mm: 1.6; SizeY_mm: 0.8; SizeZ_mm: 1; AEC Category: Q200; AEC Qualified: Y
R93 R94 = CMP-0017787-2: RES, 0.27, 1%, 0.25 W, 1206; PartNumber: ERJ-8RQFR27V; Manufacturer: Panasonic; Value: 0.27; Res_ohm: 2.7d; Value_Code: R270; Power_W: 250mW; TempCo: 250 ppm/C; EIA_Code: E96; U/M: EA; AEC Category: Q200; SizeArea_mm2: 5.12; SizeX_mm: 3.2; SizeY_mm: 1.6; SizeZ_mm: 1.35
R95 = CMP-0022547-5: RES, 665, 1%, 0.1 W, AEC-Q200 Grade 0, 0603; PartNumber: CRCW0603665RFKEA; Manufacturer: Vishay-Dale; Value: 665; Value_Code: 665R; Power_W: 100mW; Value2: 0.1W; VDC_V: 75V; TempCo: 100 ppm/C; EIA_Code: E96; AEC Category: Q200; AEC Qualified: Y; AEC Grade: 0; SizeArea_mm2: 1.28; SizeX_mm: 1.6; SizeY_mm: 0.8; SizeZ_mm: 1
R96 R97 = CMP-0021998-4: RES, 10.0 k, 1%, 0.1 W, AEC-Q200 Grade 0, 0603; PartNumber: CRCW060310K0FKEA; Manufacturer: Vishay-Dale; Value: 10.0k; Res_ohm: 10k; Value_Code: 10k0; Power_W: 100mW; Value2: 0.1W; VDC_V: 75V; TempCo: 100 ppm/C; SizeArea_mm2: 1.28; SizeX_mm: 1.6; SizeY_mm: 0.8; SizeZ_mm: 1; EIA_Code: E96; AEC Category: Q200; AEC Qualified: Y; AEC Grade: 0
R98 = CMP-0022109-5: RES, 1.00 k, 1%, 0.1 W, AEC-Q200 Grade 0, 0603; PartNumber: CRCW06031K00FKEA; Manufacturer: Vishay-Dale; Value: 1.00k; Res_ohm: 1k; Value_Code: 1k00; Power_W: 100mW; Value2: 0.1W; VDC_V: 75V; TempCo: 100 ppm/C; SizeArea_mm2: 1.28; SizeX_mm: 1.6; SizeY_mm: 0.8; SizeZ_mm: 1; EIA_Code: E96; AEC Category: Q200; AEC Qualified: Y; AEC Grade: 0
R99 = CMP-0022374-4: RES, 3.24 k, 1%, 0.1 W, AEC-Q200 Grade 0, 0603; PartNumber: CRCW06033K24FKEA; Manufacturer: Vishay-Dale; Value: 3.24k; Value_Code: 3k24; Power_W: 100mW; Value2: 0.1W; VDC_V: 75V; TempCo: 100 ppm/C; EIA_Code: E96; AEC Category: Q200; AEC Qualified: Y; AEC Grade: 0; SizeArea_mm2: 1.28; SizeX_mm: 1.6; SizeY_mm: 0.8; SizeZ_mm: 1
T3 = CMP-0030440-2: Transformer, 35 uH, SMT; Manufacturer: Pulse Engineering; ValueDisplayed: 35uH; Value: 35uH; Lp: 35; DCR_ohm: 2.3d; Ns1toNp: 0.21; Ns3toNp: 0.421; Ind_H: 35µH; LeakageInd_H: 500nH; Rsec1_ohm: 0.0103; Rsec3_ohm: 4.8d
U7 = CMP-0066105-1: 13-100V Wide Vin, Current Mode PWM Boost Controller, DGS0010A (VSSOP-10); Manufacturer: Texas Instruments; CompType: IC; Green_Lifecycle: Active; Green_REACh: Passed; SizeArea_mm2: 14.7; SizeAreaWB_mm2: 23.6; SizeX_mm: 4.9; SizeY_mm: 3.0; SizeZ_mm: 1.1; U/M: EA
U8 = CMP-0006164-3: Optocoupler, 3.75 kV, 80-160% CTR, SMT; Manufacturer: Fairchild Semiconductor; CTR (Min): 80%; CTR (Max): 160%; Voltage_Isolation_Vrms: 3.75kV; SizeAreaWB_mm2: 4; SizeArea_mm2: 1
U9 = CMP-0032952-1: Low Voltage Adjustable Precision Shunt Regulator, 39 ppm / degC, 15 mA, -40 to 85 degC, 5-pin SOT-23 (DBV), Green (RoHS & no Sb/Br); Manufacturer: Texas Instruments; Initial Accuracy @ 25/deg C(%): 1; Min Iz for Regulation(uA): 80; VO Adj(Min)(V): 1.24; VO Adj(Max)(V): 6; SubFamily: Shunt Voltage Reference; Temp Coeff(Max)(ppm/ degree C): 129; Temp Coeff(Typ)(ppm/ degree C): 39; Rating: Catalog; Iout/Iz(Max)(mA): 15

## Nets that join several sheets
GND: PMP20859_RevF_SH2 (9 pins), PMP20859_RevF_SH3 (21 pins)
PWRGND: PMP20859_RevF_SH2 (33 pins), PMP20859_RevF_SH3 (22 pins)
SS: PMP20859_RevF_SH2 (Q9.3), PMP20859_RevF_SH3 (C60.2 R82.1 R86.2 U7.7)
VDD: PMP20859_RevF_SH1 (C2.1 C14.1 L1.2 L3.2), PMP20859_RevF_SH2 (37 pins), PMP20859_RevF_SH3 (5 pins)
VOUT: PMP20859_RevF_SH2 (R56.2), PMP20859_RevF_SH3 (5 pins)
VSS_1: PMP20859_RevF_SH1 (C2.2 L2.2), PMP20859_RevF_SH2 (10 pins)
VSS_2: PMP20859_RevF_SH1 (C14.2 L4.2), PMP20859_RevF_SH2 (10 pins)

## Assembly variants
001: not fitted C68 C69 C70 D35 D36 D37 D38 D39 D40 D41 D42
